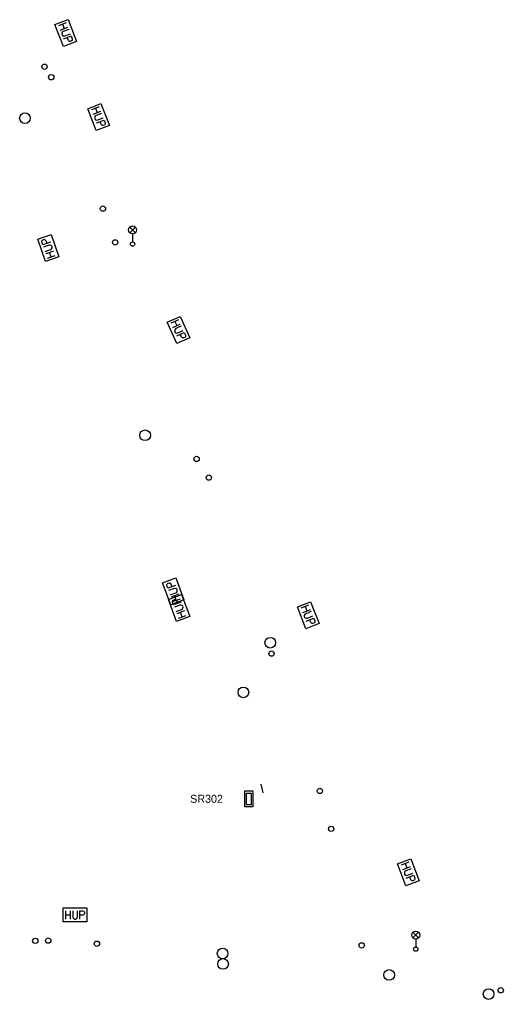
# Model space of a CAD drawing. Extents: x -762500 to -761250, y -1152983 to -1152297.
# Drawn here: x -761480.4 to -761435.1, y -1152527.8 to -1152435.9 of the extents above; entities that cross this region are included whole.
import ezdxf

# ---------------------------------------------------------------- set-up
doc = ezdxf.new("R2010")
doc.units = 0
for name, color, linetype in [('Vrstva 1', 7, 'Continuous'), ('Vrstva 11', 7, 'Continuous'), ('Vrstva 2', 7, 'Continuous'), ('Vrstva 9', 7, 'Continuous')]:
    doc.layers.add(name, color=color, linetype=linetype)

msp = doc.modelspace()

# ---------------------------------------------------------------- linework, layer by layer
at = {"layer": 'Vrstva 1'}
for points in [[(-761459.311, -1152509.759), (-761459.329, -1152508.259), (-761458.579, -1152508.25), (-761458.561, -1152509.75)], [(-761459.164, -1152509.557), (-761459.176, -1152508.457), (-761458.726, -1152508.452), (-761458.714, -1152509.552)]]:
    msp.add_lwpolyline(points, close=True, dxfattribs=at)
at = {"layer": 'Vrstva 11'}
msp.add_line((-761457.82, -1152507.62), (-761457.62, -1152508.44), dxfattribs=at)
at = {"layer": 'Vrstva 9'}
for p, q in [((-761470.094, -1152455.928), (-761469.566, -1152455.4)), ((-761469.558, -1152455.925), (-761470.086, -1152455.396)), ((-761469.83, -1152456.04), (-761469.83, -1152456.79)), ((-761443.584, -1152522.028), (-761443.056, -1152521.5)), ((-761443.048, -1152522.025), (-761443.576, -1152521.496)), ((-761443.32, -1152522.14), (-761443.32, -1152522.89))]:
    msp.add_line(p, q, dxfattribs=at)
for points in [[(-761475.873, -1152435.949), (-761475.083, -1152438.002), (-761476.315, -1152438.477), (-761477.105, -1152436.423), (-761475.873, -1152435.949)], [(-761476.051, -1152436.253), (-761476.769, -1152436.53)], [(-761476.611, -1152436.942), (-761475.892, -1152436.666)], [(-761475.814, -1152436.869), (-761476.329, -1152437.068), (-761476.419, -1152437.135), (-761476.462, -1152437.225), (-761476.463, -1152437.325), (-761476.441, -1152437.384), (-761476.373, -1152437.457), (-761476.282, -1152437.49), (-761476.17, -1152437.48), (-761475.655, -1152437.282)], [(-761476.39, -1152436.384), (-761476.231, -1152436.796)], [(-761476.295, -1152437.762), (-761475.577, -1152437.485)], [(-761475.577, -1152437.485), (-761475.474, -1152437.752), (-761475.475, -1152437.851), (-761475.497, -1152437.895), (-761475.553, -1152437.95), (-761475.656, -1152437.989), (-761475.735, -1152437.987), (-761475.78, -1152437.968), (-761475.847, -1152437.896), (-761475.95, -1152437.629)], [(-761472.793, -1152443.829), (-761472.003, -1152445.882), (-761473.235, -1152446.357), (-761474.025, -1152444.303), (-761472.793, -1152443.829)], [(-761472.971, -1152444.133), (-761473.689, -1152444.41)], [(-761473.31, -1152444.264), (-761473.151, -1152444.676)], [(-761473.531, -1152444.822), (-761472.812, -1152444.546)], [(-761472.734, -1152444.749), (-761473.249, -1152444.948), (-761473.339, -1152445.015), (-761473.382, -1152445.105), (-761473.383, -1152445.205), (-761473.361, -1152445.264), (-761473.293, -1152445.337), (-761473.202, -1152445.37), (-761473.09, -1152445.36), (-761472.575, -1152445.162)], [(-761473.215, -1152445.642), (-761472.497, -1152445.365)], [(-761472.497, -1152445.365), (-761472.394, -1152445.632), (-761472.395, -1152445.731), (-761472.417, -1152445.775), (-761472.473, -1152445.83), (-761472.576, -1152445.869), (-761472.655, -1152445.867), (-761472.7, -1152445.848), (-761472.767, -1152445.776), (-761472.87, -1152445.509)], [(-761477.995, -1152458.613), (-761478.718, -1152456.535), (-761477.471, -1152456.101), (-761476.749, -1152458.179), (-761477.995, -1152458.613)], [(-761478.242, -1152457.068), (-761478.336, -1152456.798), (-761478.331, -1152456.699), (-761478.308, -1152456.656), (-761478.25, -1152456.603), (-761478.146, -1152456.566), (-761478.067, -1152456.572), (-761478.023, -1152456.591), (-761477.958, -1152456.666), (-761477.864, -1152456.936)], [(-761477.514, -1152456.815), (-761478.242, -1152457.068)], [(-761478.025, -1152457.691), (-761477.503, -1152457.51), (-761477.412, -1152457.445), (-761477.365, -1152457.357), (-761477.361, -1152457.257), (-761477.381, -1152457.197), (-761477.447, -1152457.122), (-761477.536, -1152457.086), (-761477.649, -1152457.092), (-761478.17, -1152457.274)], [(-761477.226, -1152457.644), (-761477.953, -1152457.897)], [(-761477.808, -1152458.314), (-761477.081, -1152458.061)], [(-761477.465, -1152458.195), (-761477.61, -1152457.778)], [(-761465.386, -1152463.771), (-761464.472, -1152465.773), (-761465.673, -1152466.321), (-761466.587, -1152464.319), (-761465.386, -1152463.771)], [(-761465.545, -1152464.086), (-761466.245, -1152464.405)], [(-761466.062, -1152464.807), (-761465.361, -1152464.488)], [(-761465.875, -1152464.236), (-761465.691, -1152464.638)], [(-761465.271, -1152464.686), (-761465.773, -1152464.915), (-761465.858, -1152464.988), (-761465.896, -1152465.08), (-761465.891, -1152465.18), (-761465.865, -1152465.238), (-761465.793, -1152465.307), (-761465.7, -1152465.334), (-761465.589, -1152465.317), (-761465.087, -1152465.088)], [(-761465.697, -1152465.606), (-761464.997, -1152465.286)], [(-761464.997, -1152465.286), (-761464.878, -1152465.547), (-761464.873, -1152465.646), (-761464.892, -1152465.691), (-761464.945, -1152465.749), (-761465.045, -1152465.794), (-761465.124, -1152465.796), (-761465.17, -1152465.781), (-761465.242, -1152465.713), (-761465.361, -1152465.452)], [(-761466.264, -1152490.805), (-761467.017, -1152488.738), (-761465.776, -1152488.286), (-761465.024, -1152490.354), (-761466.264, -1152490.805)], [(-761466.532, -1152489.264), (-761466.63, -1152488.995), (-761466.627, -1152488.896), (-761466.605, -1152488.853), (-761466.547, -1152488.799), (-761466.444, -1152488.762), (-761466.365, -1152488.766), (-761466.321, -1152488.785), (-761466.254, -1152488.859), (-761466.157, -1152489.127)], [(-761465.809, -1152489.001), (-761466.532, -1152489.264)], [(-761466.307, -1152489.884), (-761465.788, -1152489.695), (-761465.697, -1152489.629), (-761465.652, -1152489.54), (-761465.649, -1152489.44), (-761465.67, -1152489.381), (-761465.737, -1152489.306), (-761465.827, -1152489.272), (-761465.939, -1152489.28), (-761466.458, -1152489.469)], [(-761465.721, -1152492.367), (-761466.478, -1152490.301), (-761465.238, -1152489.847), (-761464.482, -1152491.913), (-761465.721, -1152492.367)], [(-761465.509, -1152489.826), (-761466.232, -1152490.089)], [(-761466.081, -1152490.504), (-761465.357, -1152490.241)], [(-761465.74, -1152490.38), (-761465.891, -1152489.965)], [(-761465.993, -1152490.826), (-761466.091, -1152490.558), (-761466.088, -1152490.458), (-761466.065, -1152490.415), (-761466.008, -1152490.361), (-761465.905, -1152490.323), (-761465.826, -1152490.327), (-761465.782, -1152490.346), (-761465.715, -1152490.42), (-761465.617, -1152490.689)], [(-761465.27, -1152490.561), (-761465.993, -1152490.826)], [(-761465.766, -1152491.446), (-761465.247, -1152491.256), (-761465.157, -1152491.19), (-761465.111, -1152491.101), (-761465.109, -1152491.001), (-761465.13, -1152490.942), (-761465.197, -1152490.867), (-761465.287, -1152490.833), (-761465.399, -1152490.841), (-761465.918, -1152491.031)], [(-761453.17, -1152490.526), (-761452.371, -1152492.576), (-761453.601, -1152493.055), (-761454.399, -1152491.005), (-761453.17, -1152490.526)], [(-761453.346, -1152490.831), (-761454.063, -1152491.11)], [(-761453.684, -1152490.962), (-761453.524, -1152491.374)], [(-761464.968, -1152491.386), (-761465.691, -1152491.651)], [(-761465.539, -1152492.066), (-761464.816, -1152491.801)], [(-761465.198, -1152491.941), (-761465.35, -1152491.526)], [(-761453.903, -1152491.522), (-761453.185, -1152491.242)], [(-761453.106, -1152491.446), (-761453.621, -1152491.646), (-761453.71, -1152491.714), (-761453.753, -1152491.804), (-761453.754, -1152491.904), (-761453.731, -1152491.963), (-761453.663, -1152492.036), (-761453.572, -1152492.068), (-761453.46, -1152492.058), (-761452.946, -1152491.857)], [(-761453.584, -1152492.34), (-761452.867, -1152492.06)], [(-761452.867, -1152492.06), (-761452.763, -1152492.327), (-761452.764, -1152492.426), (-761452.785, -1152492.47), (-761452.841, -1152492.525), (-761452.944, -1152492.565), (-761453.023, -1152492.563), (-761453.067, -1152492.544), (-761453.135, -1152492.472), (-761453.239, -1152492.206)], [(-761443.788, -1152514.632), (-761443.005, -1152516.688), (-761444.238, -1152517.158), (-761445.022, -1152515.102), (-761443.788, -1152514.632)], [(-761443.967, -1152514.936), (-761444.686, -1152515.21)], [(-761444.306, -1152515.065), (-761444.149, -1152515.478)], [(-761444.529, -1152515.623), (-761443.809, -1152515.349)], [(-761443.732, -1152515.552), (-761444.248, -1152515.749), (-761444.337, -1152515.816), (-761444.381, -1152515.906), (-761444.383, -1152516.006), (-761444.361, -1152516.065), (-761444.293, -1152516.139), (-761444.202, -1152516.171), (-761444.09, -1152516.162), (-761443.574, -1152515.966)], [(-761444.216, -1152516.443), (-761443.497, -1152516.169)], [(-761443.497, -1152516.169), (-761443.395, -1152516.437), (-761443.397, -1152516.536), (-761443.419, -1152516.579), (-761443.475, -1152516.634), (-761443.578, -1152516.673), (-761443.657, -1152516.67), (-761443.702, -1152516.652), (-761443.769, -1152516.579), (-761443.871, -1152516.312)], [(-761476.32, -1152519.22), (-761474.12, -1152519.22), (-761474.12, -1152520.54), (-761476.32, -1152520.54), (-761476.32, -1152519.22)], [(-761476.1, -1152519.495), (-761476.1, -1152520.265)], [(-761475.658, -1152520.265), (-761475.658, -1152519.495)], [(-761475.44, -1152519.495), (-761475.44, -1152520.047), (-761475.409, -1152520.155), (-761475.341, -1152520.228), (-761475.248, -1152520.265), (-761475.185, -1152520.265), (-761475.092, -1152520.228), (-761475.029, -1152520.155), (-761474.998, -1152520.047), (-761474.998, -1152519.495)], [(-761474.78, -1152519.495), (-761474.494, -1152519.495), (-761474.402, -1152519.532), (-761474.369, -1152519.568), (-761474.338, -1152519.64), (-761474.338, -1152519.75), (-761474.369, -1152519.823), (-761474.402, -1152519.858), (-761474.494, -1152519.895), (-761474.78, -1152519.895)], [(-761474.78, -1152520.265), (-761474.78, -1152519.495)], [(-761476.1, -1152519.858), (-761475.658, -1152519.858)]]:
    msp.add_lwpolyline(points, dxfattribs=at)
for centre, radius in [((-761478.08, -1152440.37), 0.25), ((-761477.45, -1152441.35), 0.25), ((-761479.91, -1152445.19), 0.5), ((-761472.61, -1152453.67), 0.25), ((-761469.83, -1152455.665), 0.375), ((-761471.46, -1152456.83), 0.25), ((-761469.83, -1152456.99), 0.2), ((-761468.66, -1152474.92), 0.5), ((-761463.84, -1152477.13), 0.25), ((-761462.69, -1152478.88), 0.25), ((-761456.94, -1152494.36), 0.5), ((-761456.82, -1152495.38), 0.25), ((-761459.46, -1152499.02), 0.5), ((-761452.3, -1152508.26), 0.25), ((-761451.24, -1152511.81), 0.25), ((-761443.32, -1152521.765), 0.375), ((-761478.94, -1152522.31), 0.25), ((-761477.73, -1152522.29), 0.25), ((-761473.17, -1152522.58), 0.25), ((-761461.4, -1152523.5), 0.5), ((-761448.38, -1152522.74), 0.25), ((-761443.32, -1152523.09), 0.2), ((-761461.36, -1152524.48), 0.5), ((-761445.81, -1152525.51), 0.5), ((-761436.49, -1152527.3), 0.5), ((-761435.36, -1152526.94), 0.25)]:
    msp.add_circle(centre, radius, dxfattribs=at)

# ---------------------------------------------------------------- texts
at = {"layer": 'Vrstva 2'}
msp.add_text('SR302', height=0.75, dxfattribs=at).set_placement((-761464.44, -1152509.37))

doc.saveas('drawing.dxf')
